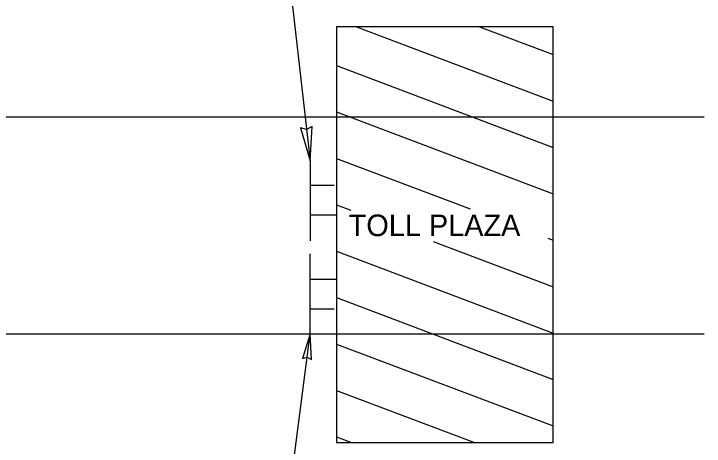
# Model space of a CAD drawing. Extents: x 46672 to 47298, y 5424 to 5742.
# Drawn here: x 47190.7 to 47280.2, y 5614.1 to 5670.1 of the extents above; entities that cross this region are included whole.
import ezdxf

# ---------------------------------------------------------------- set-up
doc = ezdxf.new("R2010")
doc.units = 0
for name, color, linetype in [('LeaderLine_dp', 7, 'Continuous'), ('RoadwayMisc', 7, 'Continuous'), ('SignSupport', 7, 'Continuous'), ('TextLabel', 7, 'Continuous')]:
    doc.layers.add(name, color=color, linetype=linetype)

msp = doc.modelspace()

# ---------------------------------------------------------------- linework, layer by layer
at = {"layer": 'LeaderLine_dp'}
for p, q in [((47223.204, 5702.264), (47229.136, 5651.07)), ((47223.204, 5583.153), (47229.136, 5628.632))]:
    msp.add_line(p, q, dxfattribs=at)
for points in [[(47229.136, 5651.07), (47229.382, 5655.496), (47228.67, 5655.093), (47227.861, 5655.313)], [(47229.136, 5628.632), (47228.151, 5625.457), (47228.743, 5625.619), (47229.291, 5625.314)]]:
    msp.add_lwpolyline(points, close=True, dxfattribs=at)
at = {"layer": 'RoadwayMisc'}
for p, q in [((47232.522, 5668.418), (47232.521, 5614.562)), ((47260.646, 5668.418), (47232.522, 5668.418)), ((47235.139, 5668.418), (47260.646, 5658.8)), ((47251.08, 5668.418), (47260.646, 5664.811)), ((47260.646, 5614.562), (47260.646, 5668.418)), ((47232.522, 5663.394), (47260.645, 5652.788)), ((47232.521, 5657.382), (47260.646, 5646.776)), ((47010.152, 5656.764), (47280.214, 5656.764)), ((47232.522, 5651.371), (47249.888, 5644.822)), ((47232.52, 5645.359), (47234.38, 5644.658)), ((47245.089, 5640.62), (47260.646, 5634.753)), ((47259.962, 5641.022), (47260.646, 5640.764)), ((47232.522, 5639.348), (47260.645, 5628.741)), ((47232.522, 5633.335), (47260.646, 5622.729)), ((47010.152, 5628.639), (47280.214, 5628.639)), ((47232.521, 5627.324), (47260.646, 5616.717)), ((47232.521, 5621.312), (47250.42, 5614.562)), ((47232.521, 5615.301), (47234.48, 5614.562)), ((47232.521, 5614.562), (47260.646, 5614.562))]:
    msp.add_line(p, q, dxfattribs=at)
at = {"layer": 'SignSupport'}
for p, q in [((47229.136, 5651.07), (47229.136, 5640.678)), ((47232.259, 5647.851), (47229.136, 5647.852)), ((47232.48, 5644), (47229.136, 5643.999)), ((47229.136, 5628.632), (47229.136, 5639.024)), ((47232.48, 5635.702), (47229.136, 5635.703)), ((47232.259, 5631.851), (47229.136, 5631.85))]:
    msp.add_line(p, q, dxfattribs=at)

# ---------------------------------------------------------------- texts
at = {"layer": 'TextLabel'}
msp.add_text('TOLL PLAZA', height=2.8, dxfattribs=at).set_placement((47234.119, 5641.301))

doc.saveas('drawing.dxf')
